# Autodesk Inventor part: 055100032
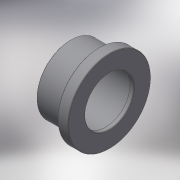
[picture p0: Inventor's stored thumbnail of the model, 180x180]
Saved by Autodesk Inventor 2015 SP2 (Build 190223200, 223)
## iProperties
Created: 2017-10
Part Number: 055100032
Material: Generic
Description: PLASSON FLANGE FLAT AD.-CEM 32
Document SubType Name: Modeling
Designer: KIM
Mass: 17.8474 g
Surface Area: 84.3816 cm^2
Volume: 17.8474 cm^3
Density: 1 g/cm^3
Appearance: Default
Author: KIM
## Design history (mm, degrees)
derived "055100.ipt"
feature "Solid1::055100.ipt"
tag "TaggingFeature1"
body "Solid1"
other parameters: "d0" = 25, "d1" = 41, "d2" = 32, "d3" = 28.8, "d4" = 7, "d5" = 22, "d8" = 0.32, "d_" = 32, "E_" = 41, "l_" = 22, "B_" = 7, "H_" = 25
